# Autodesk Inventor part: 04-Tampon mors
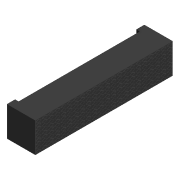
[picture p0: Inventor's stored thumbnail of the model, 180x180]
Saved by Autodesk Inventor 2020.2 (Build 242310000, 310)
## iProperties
Created: 2022-02
Part Number: 04-Tampon mors
Material: Caoutchouc
Document SubType Name: Modeling
Designer: Philippe
Density: 0.93 g/cm^3
Appearance: Caoutchouc - Noir
Author: Philippe
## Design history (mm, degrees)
sketch "Esquisse1"
  geometry: L1 (-12, 6.5)-(0, 6.5); L2 (0, 6.5)-(0, -6.5); L3 (0, -6.5)-(-12, -6.5); L4 (-12, -6.5)-(-12, 6.5); 2 further points
  constraints: 8 end point, 2 parallel, 1 coincident, 1 horizontal, 1 midpoint, 1 perpendicular
  dimensions: "d0" = 13 distance of L3.end L1.start; "d1" = 12 distance of L2.end L3.end
extrude "Extrusion1" new body sketch "Esquisse1" stored distance "d2" = 74; taper "d3" = 0 deg
feature "Coque1" dims "d4" = 2
sketch "Esquisse2"
  geometry: L1 (0, 78)-(0, 0) reference; L2 (0, 73.5)-(2, 73.5); L3 (2, 73.5)-(2, 4.5); L4 (2, 4.5)-(0, 4.5); L5 (0, 4.5)-(0, 73.5); 3 further points
  constraints: 8 end point, 2 midpoint, 2 parallel, 1 horizontal, 1 perpendicular, 1 point on line
  dimensions: "d5" = 2 distance of L2.start L2.end; "d6" = 69 distance of L2.end L3.end
extrude "Extrusion2" cut sketch "Esquisse2" extent not by distance; stored distance "d7" = 0; taper "d8" = 0 deg
sketch "Esquisse3"
  geometry: L1 (0.25, 16)-(1.75, 16.75); L2 (1.75, 16.75)-(3.25, 16); L3 (3.25, 16)-(1.75, 15.25); L4 (1.75, 15.25)-(0.25, 16); L5 (0.25, 16)-(3.25, 16); L6 (1.75, 16.75)-(1.75, 15.25); L7 (0, 0)-(0, 17) reference; L8 (0, 17)-(78, 17) reference; 2 further points
  constraints: 12 end point, 2 parallel, 1 horizontal, 1 horizontal alignment, 1 midpoint, 1 vertical alignment
  dimensions: "d9" = 1.5 distance of L1.end L3.end; "d10" = 3 distance of L2.end L1.start; "d11" = 1.75 distance from line of L7 point (1.75, 16); "d12" = 1 distance from line of L8 point (1.75, 16)
extrude "Extrusion3" join sketch "Esquisse3" distance "d13" = 0.2; taper "d14" = 0 deg
node "Solide1"
pattern_linear "Réseau rectangulaire1" dims "d17" = 3.55, "d20" = 1.85
